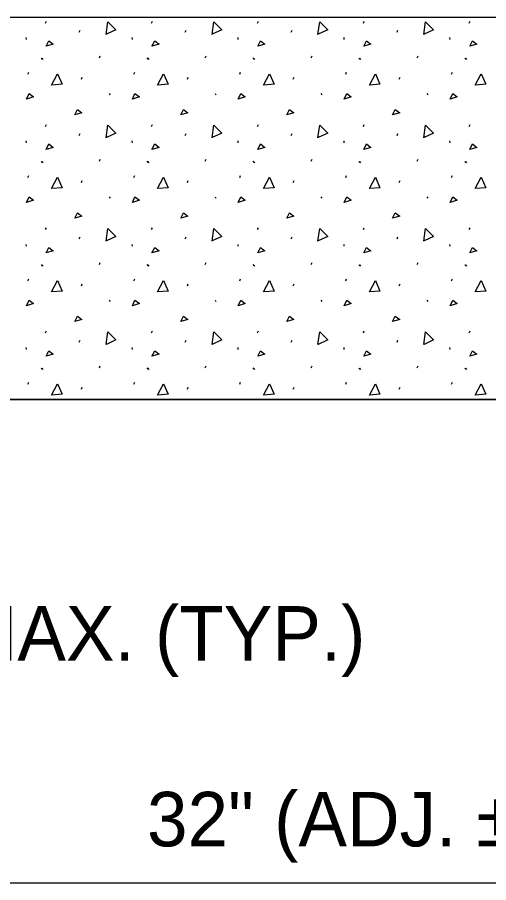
# Model space of a CAD drawing. Extents: x 49991.4 to 50021, y 49987.6 to 50011.4.
# Drawn here: x 50012.708 to 50013.228, y 49990.392 to 49991.345 of the extents above; entities that cross this region are included whole.
import ezdxf

# ---------------------------------------------------------------- set-up
doc = ezdxf.new("R2010")
doc.units = 0
for name, color, linetype in [('Level 1', 7, 'Continuous'), ('Level 2', 7, 'Continuous'), ('Level 3', 7, 'Continuous')]:
    doc.layers.add(name, color=color, linetype=linetype)

msp = doc.modelspace()

# ---------------------------------------------------------------- linework, layer by layer
at = {"layer": 'Level 1'}
for p, q in [((50012.2443, 49991.3452), (50014.4739, 49991.3452)), ((50012.2443, 49991.3452), (50014.4739, 49991.3452)), ((50012.7395, 49991.3389), (50012.7404, 49991.3411)), ((50012.8562, 49991.3389), (50012.8571, 49991.3411)), ((50012.9728, 49991.3389), (50012.9738, 49991.3411)), ((50013.0895, 49991.3389), (50013.0905, 49991.3411)), ((50013.2062, 49991.3389), (50013.2072, 49991.3411)), ((50012.7765, 49991.3289), (50012.7775, 49991.3311)), ((50012.8932, 49991.3289), (50012.8942, 49991.3311)), ((50013.0099, 49991.3289), (50013.0109, 49991.3311)), ((50013.1266, 49991.3289), (50013.1275, 49991.3311)), ((50012.7177, 49991.3228), (50012.718, 49991.3206)), ((50012.8344, 49991.3228), (50012.8347, 49991.3206)), ((50012.9511, 49991.3228), (50012.9513, 49991.3206)), ((50013.0678, 49991.3228), (50013.068, 49991.3206)), ((50013.1845, 49991.3228), (50013.1847, 49991.3206)), ((50012.7344, 49991.3007), (50012.7353, 49991.2992)), ((50012.7353, 49991.3001), (50012.7363, 49991.2987)), ((50012.7987, 49991.3007), (50012.7996, 49991.3029)), ((50012.851, 49991.3007), (50012.852, 49991.2992)), ((50012.852, 49991.3001), (50012.853, 49991.2987)), ((50012.9154, 49991.3007), (50012.9163, 49991.3029)), ((50012.9677, 49991.3007), (50012.9687, 49991.2992)), ((50012.9687, 49991.3001), (50012.9697, 49991.2987)), ((50013.032, 49991.3007), (50013.033, 49991.3029)), ((50013.0844, 49991.3007), (50013.0854, 49991.2992)), ((50013.0854, 49991.3001), (50013.0864, 49991.2987)), ((50013.1487, 49991.3007), (50013.1497, 49991.3029)), ((50013.2011, 49991.3007), (50013.2021, 49991.2992)), ((50013.2021, 49991.3001), (50013.2031, 49991.2987)), ((50012.72, 49991.2826), (50012.721, 49991.2848)), ((50012.7789, 49991.277), (50012.7799, 49991.2792)), ((50012.8367, 49991.2826), (50012.8376, 49991.2848)), ((50012.8956, 49991.277), (50012.8966, 49991.2792)), ((50012.9534, 49991.2826), (50012.9543, 49991.2848)), ((50013.0123, 49991.277), (50013.0133, 49991.2792)), ((50013.07, 49991.2826), (50013.071, 49991.2848)), ((50013.129, 49991.277), (50013.13, 49991.2792)), ((50013.1867, 49991.2826), (50013.1877, 49991.2848)), ((50012.8094, 49991.2614), (50012.8104, 49991.26)), ((50012.9261, 49991.2614), (50012.927, 49991.26)), ((50013.0428, 49991.2614), (50013.0437, 49991.26)), ((50013.1595, 49991.2614), (50013.1604, 49991.26)), ((50012.7395, 49991.2251), (50012.7404, 49991.2273)), ((50012.8562, 49991.2251), (50012.8571, 49991.2273)), ((50012.9728, 49991.2251), (50012.9738, 49991.2273)), ((50013.0895, 49991.2251), (50013.0905, 49991.2273)), ((50013.2062, 49991.2251), (50013.2072, 49991.2273)), ((50012.7765, 49991.2152), (50012.7775, 49991.2173)), ((50012.8932, 49991.2152), (50012.8942, 49991.2173)), ((50013.0099, 49991.2152), (50013.0109, 49991.2173)), ((50013.1266, 49991.2152), (50013.1275, 49991.2173)), ((50012.7177, 49991.209), (50012.718, 49991.2068)), ((50012.8344, 49991.209), (50012.8347, 49991.2068)), ((50012.9511, 49991.209), (50012.9513, 49991.2068)), ((50013.0678, 49991.209), (50013.068, 49991.2068)), ((50013.1845, 49991.209), (50013.1847, 49991.2068)), ((50012.7344, 49991.1869), (50012.7353, 49991.1854)), ((50012.7353, 49991.1863), (50012.7363, 49991.1849)), ((50012.7987, 49991.1869), (50012.7996, 49991.1891)), ((50012.851, 49991.1869), (50012.852, 49991.1854)), ((50012.852, 49991.1863), (50012.853, 49991.1849)), ((50012.9154, 49991.1869), (50012.9163, 49991.1891)), ((50012.9677, 49991.1869), (50012.9687, 49991.1854)), ((50012.9687, 49991.1863), (50012.9697, 49991.1849)), ((50013.032, 49991.1869), (50013.033, 49991.1891)), ((50013.0844, 49991.1869), (50013.0854, 49991.1854)), ((50013.0854, 49991.1863), (50013.0864, 49991.1849)), ((50013.1487, 49991.1869), (50013.1497, 49991.1891)), ((50013.2011, 49991.1869), (50013.2021, 49991.1854)), ((50013.2021, 49991.1863), (50013.2031, 49991.1849)), ((50012.72, 49991.1688), (50012.721, 49991.171)), ((50012.7789, 49991.1632), (50012.7799, 49991.1654)), ((50012.8367, 49991.1688), (50012.8376, 49991.171)), ((50012.8956, 49991.1632), (50012.8966, 49991.1654)), ((50012.9534, 49991.1688), (50012.9543, 49991.171)), ((50013.0123, 49991.1632), (50013.0133, 49991.1654)), ((50013.07, 49991.1688), (50013.071, 49991.171)), ((50013.129, 49991.1632), (50013.13, 49991.1654)), ((50013.1867, 49991.1688), (50013.1877, 49991.171)), ((50012.8094, 49991.1477), (50012.8104, 49991.1462)), ((50012.9261, 49991.1477), (50012.927, 49991.1462)), ((50013.0428, 49991.1477), (50013.0437, 49991.1462)), ((50013.1595, 49991.1477), (50013.1604, 49991.1462)), ((50012.7395, 49991.1114), (50012.7404, 49991.1135)), ((50012.8562, 49991.1114), (50012.8571, 49991.1135)), ((50012.9728, 49991.1114), (50012.9738, 49991.1135)), ((50013.0895, 49991.1114), (50013.0905, 49991.1135)), ((50013.2062, 49991.1114), (50013.2072, 49991.1135)), ((50012.7765, 49991.1014), (50012.7775, 49991.1036)), ((50012.8932, 49991.1014), (50012.8942, 49991.1036)), ((50013.0099, 49991.1014), (50013.0109, 49991.1036)), ((50013.1266, 49991.1014), (50013.1275, 49991.1036)), ((50012.7177, 49991.0952), (50012.718, 49991.0931)), ((50012.8344, 49991.0952), (50012.8347, 49991.0931)), ((50012.9511, 49991.0952), (50012.9513, 49991.0931)), ((50013.0678, 49991.0952), (50013.068, 49991.0931)), ((50013.1845, 49991.0952), (50013.1847, 49991.0931)), ((50012.7344, 49991.0731), (50012.7353, 49991.0716)), ((50012.7353, 49991.0726), (50012.7363, 49991.0711)), ((50012.7987, 49991.0731), (50012.7996, 49991.0753)), ((50012.851, 49991.0731), (50012.852, 49991.0716)), ((50012.852, 49991.0726), (50012.853, 49991.0711)), ((50012.9154, 49991.0731), (50012.9163, 49991.0753)), ((50012.9677, 49991.0731), (50012.9687, 49991.0716)), ((50012.9687, 49991.0726), (50012.9697, 49991.0711)), ((50013.032, 49991.0731), (50013.033, 49991.0753)), ((50013.0844, 49991.0731), (50013.0854, 49991.0716)), ((50013.0854, 49991.0726), (50013.0864, 49991.0711)), ((50013.1487, 49991.0731), (50013.1497, 49991.0753)), ((50013.2011, 49991.0731), (50013.2021, 49991.0716)), ((50013.2021, 49991.0726), (50013.2031, 49991.0711)), ((50012.72, 49991.0551), (50012.721, 49991.0572)), ((50012.7789, 49991.0494), (50012.7799, 49991.0516)), ((50012.8367, 49991.0551), (50012.8376, 49991.0572)), ((50012.8956, 49991.0494), (50012.8966, 49991.0516)), ((50012.9534, 49991.0551), (50012.9543, 49991.0572)), ((50013.0123, 49991.0494), (50013.0133, 49991.0516)), ((50013.07, 49991.0551), (50013.071, 49991.0572)), ((50013.129, 49991.0494), (50013.13, 49991.0516)), ((50013.1867, 49991.0551), (50013.1877, 49991.0572)), ((50012.8094, 49991.0339), (50012.8104, 49991.0324)), ((50012.9261, 49991.0339), (50012.927, 49991.0324)), ((50013.0428, 49991.0339), (50013.0437, 49991.0324)), ((50013.1595, 49991.0339), (50013.1604, 49991.0324)), ((50012.7395, 49990.9976), (50012.7404, 49990.9998)), ((50012.8562, 49990.9976), (50012.8571, 49990.9998)), ((50012.9728, 49990.9976), (50012.9738, 49990.9998)), ((50013.0895, 49990.9976), (50013.0905, 49990.9998)), ((50013.2062, 49990.9976), (50013.2072, 49990.9998)), ((50012.7765, 49990.9876), (50012.7775, 49990.9898)), ((50012.8932, 49990.9876), (50012.8942, 49990.9898)), ((50013.0099, 49990.9876), (50013.0109, 49990.9898)), ((50013.1266, 49990.9876), (50013.1275, 49990.9898)), ((50012.7177, 49990.9815), (50012.718, 49990.9793)), ((50012.8344, 49990.9815), (50012.8347, 49990.9793)), ((50012.9511, 49990.9815), (50012.9513, 49990.9793)), ((50013.0678, 49990.9815), (50013.068, 49990.9793)), ((50013.1845, 49990.9815), (50013.1847, 49990.9793)), ((50012.7344, 49990.9593), (50012.7353, 49990.9579)), ((50012.7353, 49990.9588), (50012.7363, 49990.9573)), ((50012.7987, 49990.9593), (50012.7996, 49990.9615)), ((50012.851, 49990.9593), (50012.852, 49990.9579)), ((50012.852, 49990.9588), (50012.853, 49990.9573)), ((50012.9154, 49990.9593), (50012.9163, 49990.9615)), ((50012.9677, 49990.9593), (50012.9687, 49990.9579)), ((50012.9687, 49990.9588), (50012.9697, 49990.9573)), ((50013.032, 49990.9593), (50013.033, 49990.9615)), ((50013.0844, 49990.9593), (50013.0854, 49990.9579)), ((50013.0854, 49990.9588), (50013.0864, 49990.9573)), ((50013.1487, 49990.9593), (50013.1497, 49990.9615)), ((50013.2011, 49990.9593), (50013.2021, 49990.9579)), ((50013.2021, 49990.9588), (50013.2031, 49990.9573)), ((50012.72, 49990.9413), (50012.721, 49990.9435)), ((50012.7789, 49990.9357), (50012.7799, 49990.9378)), ((50012.8367, 49990.9413), (50012.8376, 49990.9435)), ((50012.8956, 49990.9357), (50012.8966, 49990.9378)), ((50012.9534, 49990.9413), (50012.9543, 49990.9435)), ((50013.0123, 49990.9357), (50013.0133, 49990.9378)), ((50013.07, 49990.9413), (50013.071, 49990.9435)), ((50013.129, 49990.9357), (50013.13, 49990.9378)), ((50013.1867, 49990.9413), (50013.1877, 49990.9435)), ((50012.1908, 49990.9242), (50014.5274, 49990.9242)), ((50014.843, 49990.9242), (50012.1908, 49990.9242)), ((50014.5274, 49990.9242), (50012.1908, 49990.9242)), ((50012.1908, 49990.9242), (50014.843, 49990.9242))]:
    msp.add_line(p, q, dxfattribs=at)
for points in [[(50012.8061, 49991.3264), (50012.8081, 49991.3404), (50012.8168, 49991.3313), (50012.8064, 49991.3265)], [(50012.9228, 49991.3264), (50012.9248, 49991.3404), (50012.9335, 49991.3313), (50012.9231, 49991.3265)], [(50013.0395, 49991.3264), (50013.0414, 49991.3404), (50013.0502, 49991.3313), (50013.0397, 49991.3265)], [(50013.1562, 49991.3264), (50013.1581, 49991.3404), (50013.1669, 49991.3313), (50013.1564, 49991.3265)], [(50012.74, 49991.3134), (50012.7429, 49991.3194), (50012.7478, 49991.3158), (50012.74, 49991.3134)], [(50012.8566, 49991.3134), (50012.8596, 49991.3194), (50012.8644, 49991.3158), (50012.8566, 49991.3134)], [(50012.9733, 49991.3134), (50012.9763, 49991.3194), (50012.9811, 49991.3158), (50012.9733, 49991.3134)], [(50013.09, 49991.3134), (50013.0929, 49991.3194), (50013.0978, 49991.3158), (50013.09, 49991.3134)], [(50013.2067, 49991.3134), (50013.2096, 49991.3194), (50013.2145, 49991.3158), (50013.2067, 49991.3134)], [(50012.746, 49991.2705), (50012.7526, 49991.2829), (50012.7577, 49991.2714), (50012.7463, 49991.2705)], [(50012.8627, 49991.2705), (50012.8693, 49991.2829), (50012.8744, 49991.2714), (50012.863, 49991.2705)], [(50012.9794, 49991.2705), (50012.986, 49991.2829), (50012.9911, 49991.2714), (50012.9797, 49991.2705)], [(50013.0961, 49991.2705), (50013.1027, 49991.2829), (50013.1078, 49991.2714), (50013.0964, 49991.2705)], [(50013.2128, 49991.2705), (50013.2194, 49991.2829), (50013.2245, 49991.2714), (50013.213, 49991.2705)], [(50012.7183, 49991.2551), (50012.7212, 49991.2612), (50012.7261, 49991.2575), (50012.7183, 49991.2551)], [(50012.835, 49991.2551), (50012.8379, 49991.2612), (50012.8428, 49991.2575), (50012.835, 49991.2551)], [(50012.9517, 49991.2551), (50012.9546, 49991.2612), (50012.9594, 49991.2575), (50012.9517, 49991.2551)], [(50013.0683, 49991.2551), (50013.0713, 49991.2612), (50013.0761, 49991.2575), (50013.0683, 49991.2551)], [(50013.185, 49991.2551), (50013.188, 49991.2612), (50013.1928, 49991.2575), (50013.185, 49991.2551)], [(50012.7717, 49991.2377), (50012.7746, 49991.2438), (50012.7795, 49991.2401), (50012.7717, 49991.2377)], [(50012.8884, 49991.2377), (50012.8913, 49991.2438), (50012.8962, 49991.2401), (50012.8884, 49991.2377)], [(50013.0051, 49991.2377), (50013.008, 49991.2438), (50013.0128, 49991.2401), (50013.0051, 49991.2377)], [(50013.1217, 49991.2377), (50013.1247, 49991.2438), (50013.1295, 49991.2401), (50013.1217, 49991.2377)], [(50012.8061, 49991.2126), (50012.8081, 49991.2266), (50012.8168, 49991.2176), (50012.8064, 49991.2127)], [(50012.9228, 49991.2126), (50012.9248, 49991.2266), (50012.9335, 49991.2176), (50012.9231, 49991.2127)], [(50013.0395, 49991.2126), (50013.0414, 49991.2266), (50013.0502, 49991.2176), (50013.0397, 49991.2127)], [(50013.1562, 49991.2126), (50013.1581, 49991.2266), (50013.1669, 49991.2176), (50013.1564, 49991.2127)], [(50012.74, 49991.1996), (50012.7429, 49991.2057), (50012.7478, 49991.202), (50012.74, 49991.1996)], [(50012.8566, 49991.1996), (50012.8596, 49991.2057), (50012.8644, 49991.202), (50012.8566, 49991.1996)], [(50012.9733, 49991.1996), (50012.9763, 49991.2057), (50012.9811, 49991.202), (50012.9733, 49991.1996)], [(50013.09, 49991.1996), (50013.0929, 49991.2057), (50013.0978, 49991.202), (50013.09, 49991.1996)], [(50013.2067, 49991.1996), (50013.2096, 49991.2057), (50013.2145, 49991.202), (50013.2067, 49991.1996)], [(50012.746, 49991.1567), (50012.7526, 49991.1691), (50012.7577, 49991.1576), (50012.7463, 49991.1567)], [(50012.8627, 49991.1567), (50012.8693, 49991.1691), (50012.8744, 49991.1576), (50012.863, 49991.1567)], [(50012.9794, 49991.1567), (50012.986, 49991.1691), (50012.9911, 49991.1576), (50012.9797, 49991.1567)], [(50013.0961, 49991.1567), (50013.1027, 49991.1691), (50013.1078, 49991.1576), (50013.0964, 49991.1567)], [(50013.2128, 49991.1567), (50013.2194, 49991.1691), (50013.2245, 49991.1576), (50013.213, 49991.1567)], [(50012.7183, 49991.1413), (50012.7212, 49991.1474), (50012.7261, 49991.1438), (50012.7183, 49991.1413)], [(50012.835, 49991.1413), (50012.8379, 49991.1474), (50012.8428, 49991.1438), (50012.835, 49991.1413)], [(50012.9517, 49991.1413), (50012.9546, 49991.1474), (50012.9594, 49991.1438), (50012.9517, 49991.1413)], [(50013.0683, 49991.1413), (50013.0713, 49991.1474), (50013.0761, 49991.1438), (50013.0683, 49991.1413)], [(50013.185, 49991.1413), (50013.188, 49991.1474), (50013.1928, 49991.1438), (50013.185, 49991.1413)], [(50012.7717, 49991.1239), (50012.7746, 49991.13), (50012.7795, 49991.1263), (50012.7717, 49991.1239)], [(50012.8884, 49991.1239), (50012.8913, 49991.13), (50012.8962, 49991.1263), (50012.8884, 49991.1239)], [(50013.0051, 49991.1239), (50013.008, 49991.13), (50013.0128, 49991.1263), (50013.0051, 49991.1239)], [(50013.1217, 49991.1239), (50013.1247, 49991.13), (50013.1295, 49991.1263), (50013.1217, 49991.1239)], [(50012.8061, 49991.0988), (50012.8081, 49991.1128), (50012.8168, 49991.1038), (50012.8064, 49991.0989)], [(50012.9228, 49991.0988), (50012.9248, 49991.1128), (50012.9335, 49991.1038), (50012.9231, 49991.0989)], [(50013.0395, 49991.0988), (50013.0414, 49991.1128), (50013.0502, 49991.1038), (50013.0397, 49991.0989)], [(50013.1562, 49991.0988), (50013.1581, 49991.1128), (50013.1669, 49991.1038), (50013.1564, 49991.0989)], [(50012.74, 49991.0858), (50012.7429, 49991.0919), (50012.7478, 49991.0882), (50012.74, 49991.0858)], [(50012.8566, 49991.0858), (50012.8596, 49991.0919), (50012.8644, 49991.0882), (50012.8566, 49991.0858)], [(50012.9733, 49991.0858), (50012.9763, 49991.0919), (50012.9811, 49991.0882), (50012.9733, 49991.0858)], [(50013.09, 49991.0858), (50013.0929, 49991.0919), (50013.0978, 49991.0882), (50013.09, 49991.0858)], [(50013.2067, 49991.0858), (50013.2096, 49991.0919), (50013.2145, 49991.0882), (50013.2067, 49991.0858)], [(50012.746, 49991.0429), (50012.7526, 49991.0553), (50012.7577, 49991.0438), (50012.7463, 49991.0429)], [(50012.8627, 49991.0429), (50012.8693, 49991.0553), (50012.8744, 49991.0438), (50012.863, 49991.0429)], [(50012.9794, 49991.0429), (50012.986, 49991.0553), (50012.9911, 49991.0438), (50012.9797, 49991.0429)], [(50013.0961, 49991.0429), (50013.1027, 49991.0553), (50013.1078, 49991.0438), (50013.0964, 49991.0429)], [(50013.2128, 49991.0429), (50013.2194, 49991.0553), (50013.2245, 49991.0438), (50013.213, 49991.0429)], [(50012.7183, 49991.0275), (50012.7212, 49991.0336), (50012.7261, 49991.03), (50012.7183, 49991.0275)], [(50012.835, 49991.0275), (50012.8379, 49991.0336), (50012.8428, 49991.03), (50012.835, 49991.0275)], [(50012.9517, 49991.0275), (50012.9546, 49991.0336), (50012.9594, 49991.03), (50012.9517, 49991.0275)], [(50013.0683, 49991.0275), (50013.0713, 49991.0336), (50013.0761, 49991.03), (50013.0683, 49991.0275)], [(50013.185, 49991.0275), (50013.188, 49991.0336), (50013.1928, 49991.03), (50013.185, 49991.0275)], [(50012.7717, 49991.0101), (50012.7746, 49991.0162), (50012.7795, 49991.0125), (50012.7717, 49991.0101)], [(50012.8884, 49991.0101), (50012.8913, 49991.0162), (50012.8962, 49991.0125), (50012.8884, 49991.0101)], [(50013.0051, 49991.0101), (50013.008, 49991.0162), (50013.0128, 49991.0125), (50013.0051, 49991.0101)], [(50013.1217, 49991.0101), (50013.1247, 49991.0162), (50013.1295, 49991.0125), (50013.1217, 49991.0101)], [(50012.8061, 49990.9851), (50012.8081, 49990.999), (50012.8168, 49990.99), (50012.8064, 49990.9851)], [(50012.9228, 49990.9851), (50012.9248, 49990.999), (50012.9335, 49990.99), (50012.9231, 49990.9851)], [(50013.0395, 49990.9851), (50013.0414, 49990.999), (50013.0502, 49990.99), (50013.0397, 49990.9851)], [(50013.1562, 49990.9851), (50013.1581, 49990.999), (50013.1669, 49990.99), (50013.1564, 49990.9851)], [(50012.74, 49990.972), (50012.7429, 49990.9781), (50012.7478, 49990.9744), (50012.74, 49990.972)], [(50012.8566, 49990.972), (50012.8596, 49990.9781), (50012.8644, 49990.9744), (50012.8566, 49990.972)], [(50012.9733, 49990.972), (50012.9763, 49990.9781), (50012.9811, 49990.9744), (50012.9733, 49990.972)], [(50013.09, 49990.972), (50013.0929, 49990.9781), (50013.0978, 49990.9744), (50013.09, 49990.972)], [(50013.2067, 49990.972), (50013.2096, 49990.9781), (50013.2145, 49990.9744), (50013.2067, 49990.972)], [(50012.746, 49990.9291), (50012.7526, 49990.9415), (50012.7577, 49990.9301), (50012.7463, 49990.9291)], [(50012.8627, 49990.9291), (50012.8693, 49990.9415), (50012.8744, 49990.9301), (50012.863, 49990.9291)], [(50012.9794, 49990.9291), (50012.986, 49990.9415), (50012.9911, 49990.9301), (50012.9797, 49990.9291)], [(50013.0961, 49990.9291), (50013.1027, 49990.9415), (50013.1078, 49990.9301), (50013.0964, 49990.9291)], [(50013.2128, 49990.9291), (50013.2194, 49990.9415), (50013.2245, 49990.9301), (50013.213, 49990.9291)]]:
    msp.add_lwpolyline(points, dxfattribs=at)
at = {"layer": 'Level 3'}
msp.add_line((50012.2174, 49990.3923), (50014.5005, 49990.3923), dxfattribs=at)

# ---------------------------------------------------------------- texts
at = {"layer": 'Level 2'}
for s, p in [('2" MAX. (TYP.)', (50012.5461, 49990.6368)), ('32" (ADJ. ±1 1/2" MIN.)', (50012.85119, 49990.4323))]:
    msp.add_text(s, height=0.06, dxfattribs=at).set_placement(p)

doc.saveas('drawing.dxf')
